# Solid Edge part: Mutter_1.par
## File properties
Dokumentum tartalom típus: 0
Last saved by: ahadarics
Revision: 76
Sűrűség: 0,000 kg/m^3
Pontosság: 0,990
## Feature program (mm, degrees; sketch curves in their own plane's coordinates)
base feature "unnamed BaseFeature 1"
thread "unnamed Thread 1"
chamfer "Letörés_1"  SetBackValue2 = 60 deg
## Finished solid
Body 1: solid body, 23 faces, 46 edges, 24 vertices.
  Faces by surface: cone 14, plane 8, cylinder 1
  Edges by curve: spline 24, circle 16, line 6
Bounding box of the edges (mm): 6.000 x 19.630 x 17.000, from (0, -9.815, -8.5) to (6, 9.815, 8.5).
Cylindrical faces by radius (mm): R4.3235 x1
Conical faces (half-angle, radius in mm at the cone's reference point): 60 deg R4.3235 x1, 60 deg R5.0163 x1, 60 deg R9.1575 x12
Planar faces by outward normal: +x 1, +z 1, -x 1, -z 1, oblique 4
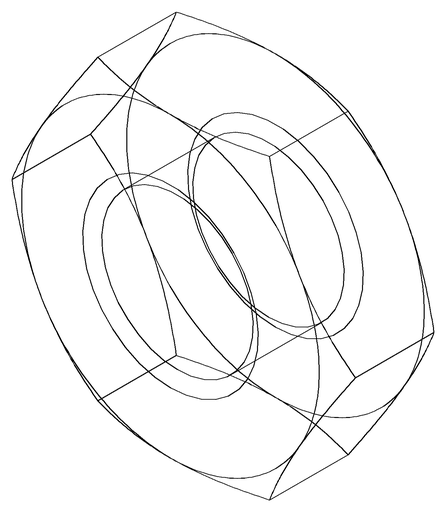
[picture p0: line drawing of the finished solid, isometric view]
